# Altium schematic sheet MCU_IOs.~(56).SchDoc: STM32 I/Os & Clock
size A4; Date: Not used; ApprovedBy: Not used; CheckedBy: Not used; Author: Not used; CompanyName: STMicroelectronics; DrawnBy: Not used; Engineer: Not used; Organization: Not used; Address1: Not used; Address2: Not used; Address3: Not used; Address4: Not used; DocumentNumber: 3; Revision: Not used; SheetNumber: 3; SheetTotal: 5
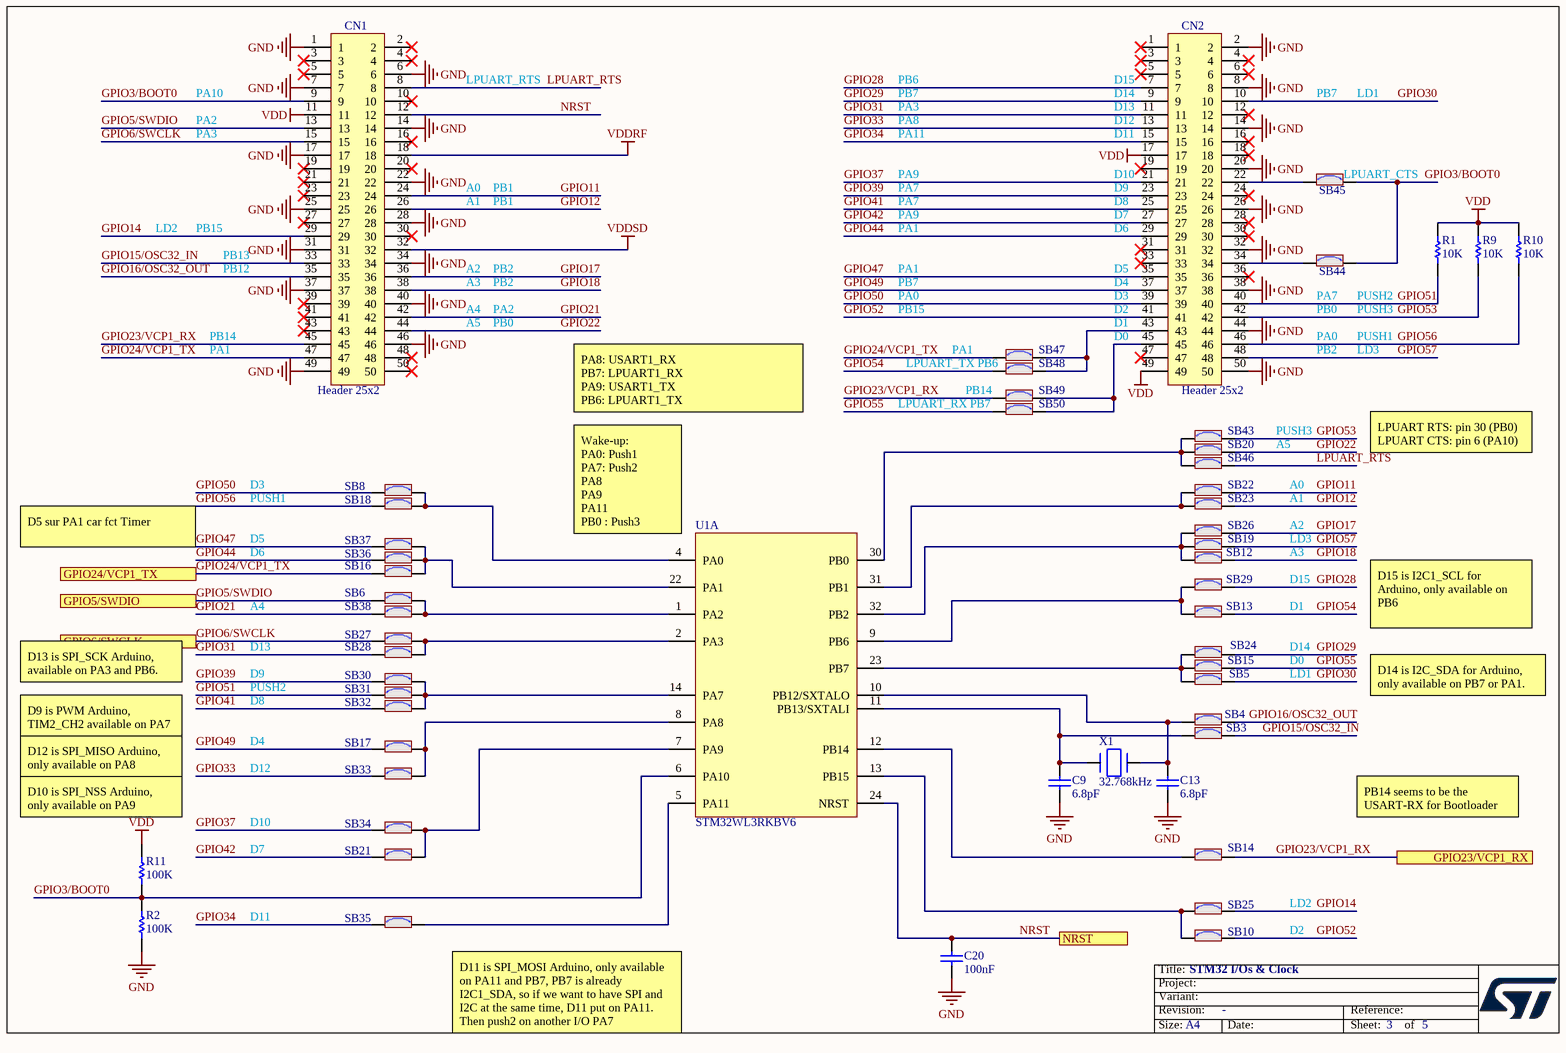
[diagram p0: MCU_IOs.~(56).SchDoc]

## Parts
C9  value 6.8pF  [C0402]  (hidden comment: Capacitor)
C13  value 6.8pF  [C0402]  (hidden comment: Capacitor)
C20  value 100nF  [C0402]  (hidden comment: Capacitor)
CN1  Header 25x2  [CON_SAMTEC_FTSH-125-02-L-DV]
CN2  Header 25x2  [CON_SAMTEC_FTSH-125-02-L-DV]
R1  value 10K  [R0402]  (hidden comment: Resistor)
R2  value 100K  [R0402]  (hidden comment: Resistor)
R9  value 10K  [R0402]  (hidden comment: Resistor)
R10  value 10K  [R0402]  (hidden comment: Resistor)
R11  value 100K  [R0402]  (hidden comment: Resistor)
SB3  SB_ON  [SOLDER-BRIDGE_R0402-0R]  (value not drawn)
SB4  SB_ON  [SOLDER-BRIDGE_R0402-0R]  (value not drawn)
SB5  SB_ON  [SOLDER-BRIDGE_R0402-0R]  (value not drawn)
SB6  SB_ON  [SOLDER-BRIDGE_R0402-0R]  (value not drawn)
SB8  SB_ON  [SOLDER-BRIDGE_R0402-0R]  (value not drawn)
SB10  SB_ON  [SOLDER-BRIDGE_R0402-0R]  (value not drawn)
SB12  SB_ON  [SOLDER-BRIDGE_R0402-0R]  (value not drawn)
SB13  SB_ON  [SOLDER-BRIDGE_R0402-0R]  (value not drawn)
SB14  SB_ON  [SOLDER-BRIDGE_R0402-0R]  (value not drawn)
SB15  SB_ON  [SOLDER-BRIDGE_R0402-0R]  (value not drawn)
SB16  SB_ON  [SOLDER-BRIDGE_R0402-0R]  (value not drawn)
SB17  SB_ON  [SOLDER-BRIDGE_R0402-0R]  (value not drawn)
SB18  SB_ON  [SOLDER-BRIDGE_R0402-0R]  (value not drawn)
SB19  SB_ON  [SOLDER-BRIDGE_R0402-0R]  (value not drawn)
SB20  SB_ON  [SOLDER-BRIDGE_R0402-0R]  (value not drawn)
SB21  SB_ON  [SOLDER-BRIDGE_R0402-0R]  (value not drawn)
SB22  SB_ON  [SOLDER-BRIDGE_R0402-0R]  (value not drawn)
SB23  SB_ON  [SOLDER-BRIDGE_R0402-0R]  (value not drawn)
SB24  SB_ON  [SOLDER-BRIDGE_R0402-0R]  (value not drawn)
SB25  SB_ON  [SOLDER-BRIDGE_R0402-0R]  (value not drawn)
SB26  SB_ON  [SOLDER-BRIDGE_R0402-0R]  (value not drawn)
SB27  SB_ON  [SOLDER-BRIDGE_R0402-0R]  (value not drawn)
SB28  SB_ON  [SOLDER-BRIDGE_R0402-0R]  (value not drawn)
SB29  SB_ON  [SOLDER-BRIDGE_R0402-0R]  (value not drawn)
SB30  SB_ON  [SOLDER-BRIDGE_R0402-0R]  (value not drawn)
SB31  SB_ON  [SOLDER-BRIDGE_R0402-0R]  (value not drawn)
SB32  SB_ON  [SOLDER-BRIDGE_R0402-0R]  (value not drawn)
SB33  SB_ON  [SOLDER-BRIDGE_R0402-0R]  (value not drawn)
SB34  SB_ON  [SOLDER-BRIDGE_R0402-0R]  (value not drawn)
SB35  SB_ON  [SOLDER-BRIDGE_R0402-0R]  (value not drawn)
SB36  SB_ON  [SOLDER-BRIDGE_R0402-0R]  (value not drawn)
SB37  SB_ON  [SOLDER-BRIDGE_R0402-0R]  (value not drawn)
SB38  SB_ON  [SOLDER-BRIDGE_R0402-0R]  (value not drawn)
SB43  SB_ON  [SOLDER-BRIDGE_R0402-0R]  (value not drawn)
SB44  SB_ON  [SOLDER-BRIDGE_R0402-0R]  (value not drawn)
SB45  SB_ON  [SOLDER-BRIDGE_R0402-0R]  (value not drawn)
SB46  SB_ON  [SOLDER-BRIDGE_R0402-0R]  (value not drawn)
SB47  SB_ON  [SOLDER-BRIDGE_R0402-0R]  (value not drawn)
SB48  SB_ON  [SOLDER-BRIDGE_R0402-0R]  (value not drawn)
SB49  SB_ON  [SOLDER-BRIDGE_R0402-0R]  (value not drawn)
SB50  SB_ON  [SOLDER-BRIDGE_R0402-0R]  (value not drawn)
U1  value STM32WL3RKBV6  [ICC_VFQFPN32-EPAD_5X5_P050]  (hidden comment: IC_STM32WL3R)  (part A of 3)
X1  value 32.768kHz  [CRY_NX2012SA_2P]  (hidden comment: XTAL_2_PINS)

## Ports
GPIO5/SWDIO, GPIO6/SWCLK, GPIO23/VCP1_RX, GPIO24/VCP1_TX, NRST

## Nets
GND: C9.1 C13.2 C20.1 CN1.1 CN1.6 CN1.7 CN1.14 CN1.17 CN1.22 CN1.25 CN1.28 CN1.31 CN1.34 CN1.37 CN1.40 CN1.46 CN1.49 CN2.2 CN2.8 CN2.14 CN2.20 CN2.26 CN2.32 CN2.38 CN2.44 CN2.50 R2.1
VDD: CN1.11 CN2.17 CN2.49 R1.2 R9.2 R10.2 R11.2
VDDRF: CN1.18
VDDSD: CN1.32
GPIO3/BOOT0: CN1.9 R2.2 R11.1 SB44.2 SB45.2 U1.6(PA10)
GPIO5/SWDIO: CN1.13 SB6.1 ; port GPIO5/SWDIO
GPIO6/SWCLK: CN1.15 SB27.1 ; port GPIO6/SWCLK
GPIO11: CN1.24 SB22.2
GPIO12: CN1.26 SB23.2
GPIO14: CN1.29 SB25.2
GPIO15/OSC32_IN: CN1.33 SB3.2
GPIO16/OSC32_OUT: CN1.35 SB4.2
GPIO17: CN1.36 SB26.2
GPIO18: CN1.38 SB12.2
GPIO21: CN1.42 SB38.1
GPIO22: CN1.44 SB20.2
GPIO23/VCP1_RX: CN1.45 SB14.2 SB49.1 ; port GPIO23/VCP1_RX
GPIO24/VCP1_TX: CN1.47 SB16.1 SB47.1 ; port GPIO24/VCP1_TX
GPIO28: CN2.7 SB29.2
GPIO29: CN2.9 SB24.2
GPIO30: CN2.10 SB5.2
GPIO31: CN2.11 SB28.1
GPIO33: CN2.13 SB33.1
GPIO34: CN2.15 SB35.1
GPIO37: CN2.21 SB34.1
GPIO39: CN2.23 SB30.1
GPIO41: CN2.25 SB32.1
GPIO42: CN2.27 SB21.1
GPIO44: CN2.29 SB36.1
GPIO47: CN2.35 SB37.1
GPIO49: CN2.37 SB17.1
GPIO50: CN2.39 SB8.1
GPIO51: CN2.40 R1.1 SB31.1
GPIO52: CN2.41 SB10.2
GPIO53: CN2.42 R9.1 SB43.2
GPIO54: SB13.2 SB48.1
GPIO55: SB15.2 SB50.1
GPIO56: CN2.46 R10.1 SB18.1
GPIO57: CN2.48 SB19.2
LPUART_RTS: CN1.8 SB46.2
NRST: C20.2 CN1.12 U1.24(NRST) ; port NRST
NetC9_2: C9.2 SB3.1 U1.11(PB13/SXTALI) X1.1(X1)
NetC13_1: C13.1 SB4.1 U1.10(PB12/SXTALO) X1.2(X2)
NetCN2_22: CN2.22 SB45.1
NetCN2_34: CN2.34 SB44.1
NetCN2_43: CN2.43 SB47.2 SB48.2
NetCN2_45: CN2.45 SB49.2 SB50.2
NetSB5_1: SB5.1 SB15.1 SB24.1 U1.23(PB7)
NetSB6_2: SB6.2 SB38.2 U1.1(PA2)
NetSB8_2: SB8.2 SB18.2 U1.4(PA0)
NetSB10_1: SB10.1 SB25.1 U1.13(PB15)
NetSB12_1: SB12.1 SB19.1 SB26.1 U1.32(PB2)
NetSB13_1: SB13.1 SB29.1 U1.9(PB6)
NetSB14_1: SB14.1 U1.12(PB14)
NetSB16_2: SB16.2 SB36.2 SB37.2 U1.22(PA1)
NetSB17_2: SB17.2 SB33.2 U1.8(PA8)
NetSB20_1: SB20.1 SB43.1 SB46.1 U1.30(PB0)
NetSB21_2: SB21.2 SB34.2 U1.7(PA9)
NetSB22_1: SB22.1 SB23.1 U1.31(PB1)
NetSB27_2: SB27.2 SB28.2 U1.2(PA3)
NetSB30_2: SB30.2 SB31.2 SB32.2 U1.14(PA7)
NetSB35_2: SB35.2 U1.5(PA11)

Not connected (* = marked no-connect by the designer): CN1 2* 3* 4* 5* 10* 16* 19* 20* 21* 23* 27* 30* 39* 41* 43* 48* 50*; CN2 1* 3* 4* 5* 6* 12* 16* 18* 19* 24* 28* 30* 31* 33* 36* 47*

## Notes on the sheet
- PA10
- LPUART_RTS
- PB7
- PB6
- PA3
- (near CN2) D13
- (near CN2) D14
- (near CN2) D15
- LD1
- PA2
- PA8
- PA11
- PA9
- (near CN2) D11
- (near CN2) D12
- (near CN2) D10
- (near SB45) LPUART_CTS
- LD2
- PB15
- A0
- A1
- PB1
- PA7
- PA1
- (near CN2) D9
- (near CN2) D8
- (near CN2) D7
- (near CN2) D6
- PB13
- PB12
- A4
- A3
- A2
- PB2
- PA0
- (near CN2) D5
- (near CN2) D4
- (near CN2) D3
- (near CN2) D2
- (near SB44) PA7
- (near SB44) PB0
- (near SB44) PUSH2
- PUSH3
- PB14
- A5
- PB0
- LPUART_TX PB6
- (near CN2) D1
- (near CN2) D0
- LD3
- PUSH1
- PA8: USART1_RX
  PB7: LPUART1_RX
  PA9: USART1_TX
  PB6: LPUART1_TX
- LPUART_RX PB7
- LPUART RTS: pin 30 (PB0)
  LPUART CTS: pin 6 (PA10)
- D3
- D5 sur PA1 car fct Timer
- D6
- D5
- (near U1) Wake-up:
  PA0: Push1
  PA7: Push2
  PA8
  PA9
  PA11
  PB0 : Push3
- D15
- D13
- D14
- D1
- D15 is I2C1_SCL for Arduino, only available on PB6
- D13 is SPI_SCK Arduino,  available on PA3 and PB6. PA3 chosen
- D8
- PUSH2
- D9
- D0
- D14 is I2C_SDA for Arduino, only available on PB7 or PA1.
  PA1 chosen
- D12 is SPI_MISO Arduino, only available on PA8
- D9 is PWM Arduino,  TIM2_CH2 available on PA7
- D4
- D12
- (near R11) D10 is SPI_NSS Arduino, only available on PA9
- D7
- D10
- PB14 seems to be the USART-RX for Bootloader
- D11
- D2
- (near SB35) D11 is SPI_MOSI Arduino, only available on PA11 and PB7, PB7 is already I2C1_SDA, so if we want to have SPI and I2C at the same time, D11 put on PA11. Then push2 on another I/O PA7

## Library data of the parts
C9 C13 = MCD-03452: Capacitor, MLCC, 6.8pF, 50V,C0G/NP0, +/-0.05pF, 0402, T=0.5mm; Part_Preference: Recommended; Manufacturer: MURATA; Manufacturer_Part_Number: GJM1555C1H6R8WB01; ShowFields: YES; ID: 5568; Component_Country_Of_Origin: Japan, Singapore
C20 = MCD-00006: Capacitor, MLCC, 100nF, 16V, X7R, +/-10%, 0402, T=0.5mm; Manufacturer_Part_Number: CC0402KRX7R7BB104; Manufacturer: YAGEO; Part_Preference: Recommended; Partial_Alternate_Internal_Part_Number: MCD-03299; Order_Code_RS: 9402047; Component_Country_Of_Origin: China; ShowFields: YES; ID: 2474
CN1 CN2 = MCD-02746: Header, 25x2, 1.27mm, VR, SMD, T=4.83mm; Part_Type: Connector; Part_Preference: Recommended; Manufacturer: SAMTEC; Manufacturer_Part_Number: FTSH-125-02-L-DV; Partial_Alternate_Internal_Part_Number: MCD-03741; ShowFields: YES; ID: 4858; Component_Country_Of_Origin: China, Costa Rica, Malaysia, USA, Vietnam
R1 R9 R10 = MCD-00053: Resistor, 10K, 0402, +/-1%, 1/16W; BMS_Part_Number: 9131590; Part_Preference: Recommended; Manufacturer: YAGEO; Manufacturer_Part_Number: RC0402FR-0710KL; Order_Code_RS: 9239359; Component_Country_Of_Origin: China; ShowFields: YES; ID: 2539
R2 R11 = MCD-00059: Resistor, 100K, 0402, +/-1%, 1/16W; Part_Preference: Recommended; Manufacturer: YAGEO; Manufacturer_Part_Number: RC0402FR-07100KL; Partial_Alternate_Internal_Part_Number: MCD-03301; Order_Code_RS: 2421891; ShowFields: YES; ID: 2533; Component_Country_Of_Origin: China
SB3-SB6 SB8 SB10 SB12-SB38 SB43-SB50 = MCD-01618: Resistor, 0R, SB0402, 5%, 0.063W; Part_Preference: Recommended; Manufacturer: YAGEO; Manufacturer_Part_Number: RC0402JR-070RL; Order_Code_RS: 618-5804; Component_Country_Of_Origin: China; ShowFields: YES; ID: 3718
U1 = MCD-04431: MCU, ARM Cortex-M0 32-bit, 128KB Flash, 16KB SRAM, With Crypto; Part_Type: IC; Part_Preference: Recommended; Manufacturer: STMICROELECTRONICS; ShowFields: YES; ID: 6547
X1 = MCD-01445: Crystal, 32.768kHz, 7pF, +/-20ppm, 80K, 2.05x1.2mm; BMS_Part_Number: 9157043; Part_Type: Crystal_Osc; Part_Preference: Recommended; Manufacturer: NDK; Manufacturer_Part_Number: NX2012SA-32.768KHz-EXS00A-MU00389; Component_Country_Of_Origin: Japan; ShowFields: YES; ID: 3545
